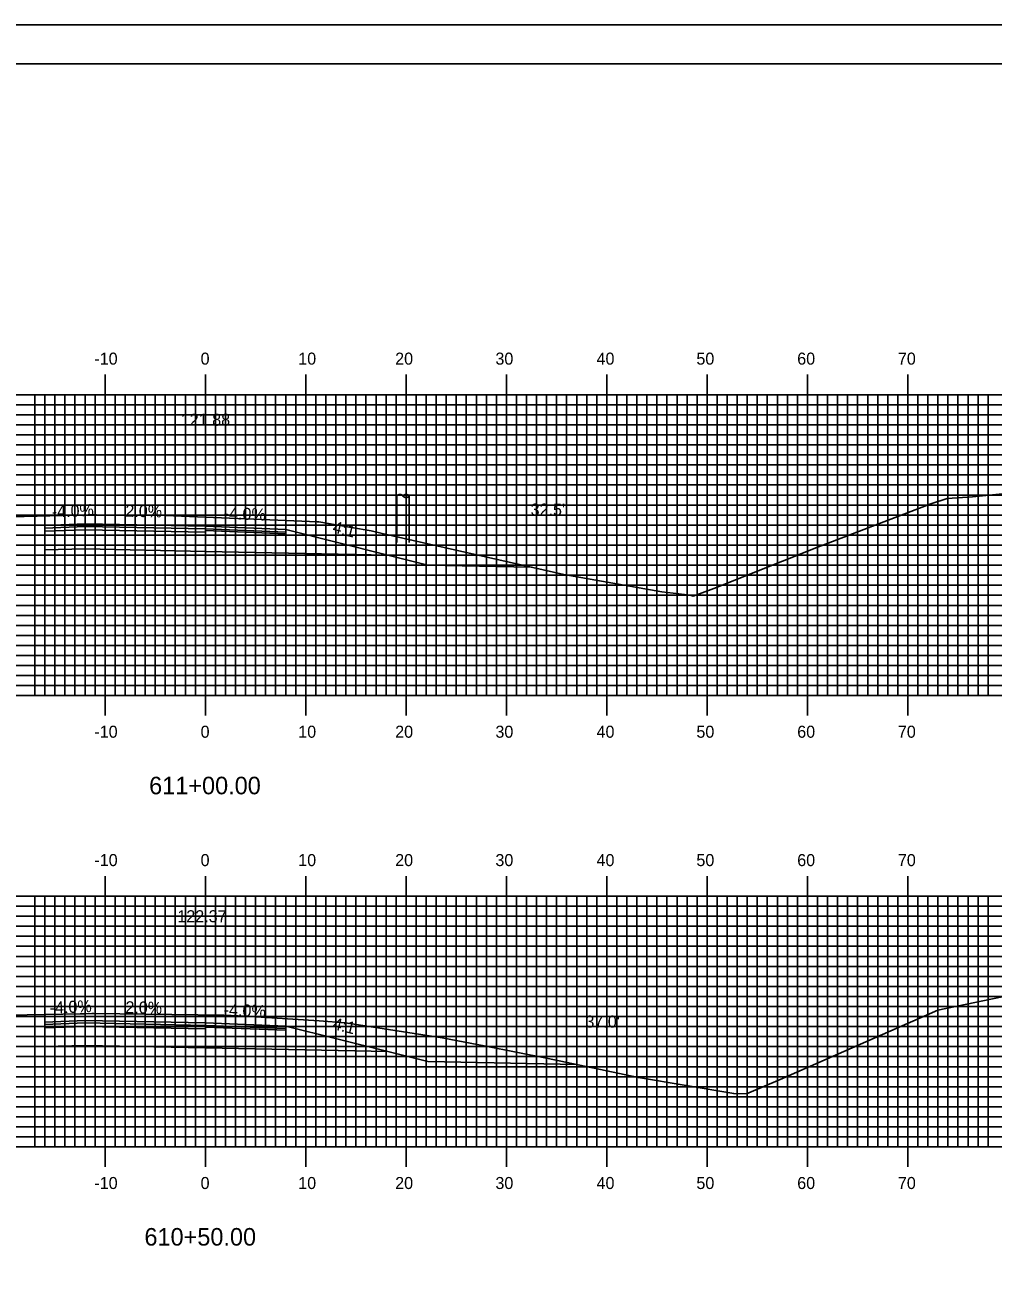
# Model space of a CAD drawing. Extents: x 843356 to 843699, y 363538 to 363758.
# Drawn here: x 843503.4 to 843599.9, y 363633.7 to 363757.6 of the extents above; entities that cross this region are included whole.
import ezdxf

# ---------------------------------------------------------------- set-up
doc = ezdxf.new("R2010")
doc.units = 0
for name, color, linetype in [('ANNOTATION', 7, 'Continuous'), ('BORDER', 7, 'Continuous'), ('D_Roadway_Centerline', 7, 'Continuous'), ('D_Roadway_Centerline_Text', 7, 'Continuous'), ('D_Roadway_Edge_Shoulder', 7, 'Continuous'), ('D_Roadway_Edge_TW', 7, 'Continuous'), ('D_Roadway_FinishedGrade', 7, 'Continuous'), ('D_Roadway_Pavement', 7, 'Continuous'), ('D_Roadway_SubGrade', 7, 'Continuous'), ('D_Text_Standard', 7, 'Continuous'), ('H_V ANNOTATION', 7, 'Continuous'), ('M_Roadway_Centerline', 7, 'Continuous'), ('MAJOR', 7, 'Continuous'), ('MINOR', 7, 'Continuous'), ('PLOT BOUNDARY', 7, 'Continuous'), ('S_Roadway_Centerline', 7, 'Continuous'), ('S_Utilities_Pole_StreetLight', 7, 'Continuous')]:
    doc.layers.add(name, color=color, linetype=linetype)

msp = doc.modelspace()

# ---------------------------------------------------------------- linework, layer by layer
at = {"layer": 'BORDER'}
msp.add_lwpolyline([(843371.82, 363543.72), (843691.82, 363543.72), (843691.82, 363753.72), (843371.82, 363753.72)], close=True, dxfattribs=at)
at = {"layer": 'D_Roadway_Centerline'}
for points in [[(843505.42, 363707.68), (843509.42, 363707.84), (843521.42, 363707.6), (843529.42, 363707.28), (843539.6, 363704.74)], [(843505.42, 363658.17), (843509.42, 363658.33), (843521.42, 363658.09), (843529.42, 363657.77), (843539.6, 363655.22)]]:
    msp.add_lwpolyline(points, dxfattribs=at)
at = {"layer": 'D_Roadway_Edge_Shoulder'}
for points in [[(843509.42, 363707.84), (843505.42, 363707.68), (843505.42, 363707.43), (843509.42, 363707.59)], [(843521.42, 363707.6), (843529.42, 363707.28), (843529.42, 363707.03), (843521.42, 363707.35)], [(843509.42, 363658.33), (843505.42, 363658.17), (843505.42, 363657.92), (843509.42, 363658.08)], [(843521.42, 363658.09), (843529.42, 363657.77), (843529.42, 363657.52), (843521.42, 363657.84)]]:
    msp.add_lwpolyline(points, close=True, dxfattribs=at)
at = {"layer": 'D_Roadway_Edge_TW'}
for points in [[(843509.42, 363707.84), (843521.42, 363707.6), (843521.42, 363707.35), (843509.42, 363707.59)], [(843509.42, 363658.33), (843521.42, 363658.09), (843521.42, 363657.84), (843509.42, 363658.08)]]:
    msp.add_lwpolyline(points, close=True, dxfattribs=at)
at = {"layer": 'D_Roadway_FinishedGrade'}
for points in [[(843539.6, 363704.74), (843543.6, 363703.74), (843553.9, 363703.53)], [(843539.6, 363655.22), (843543.6, 363654.22), (843558.44, 363653.93)]]:
    msp.add_lwpolyline(points, dxfattribs=at)
at = {"layer": 'D_Roadway_Pavement'}
for points in [[(843509.42, 363707.59), (843505.42, 363707.43), (843505.42, 363707.1), (843509.42, 363707.26)], [(843509.42, 363707.59), (843521.42, 363707.35), (843521.42, 363707.02), (843509.42, 363707.26)], [(843521.42, 363707.35), (843529.42, 363707.03), (843529.42, 363706.86), (843521.42, 363707.18)], [(843509.42, 363658.08), (843505.42, 363657.92), (843505.42, 363657.58), (843509.42, 363657.74)], [(843509.42, 363658.08), (843521.42, 363657.84), (843521.42, 363657.5), (843509.42, 363657.74)], [(843521.42, 363657.84), (843529.42, 363657.52), (843529.42, 363657.35), (843521.42, 363657.67)]]:
    msp.add_lwpolyline(points, close=True, dxfattribs=at)
for points in [[(843521.42, 363707.35), (843521.42, 363707.02)], [(843521.42, 363707.35), (843521.42, 363707.02)], [(843521.42, 363657.84), (843521.42, 363657.5)], [(843521.42, 363657.84), (843521.42, 363657.5)]]:
    msp.add_lwpolyline(points, dxfattribs=at)
at = {"layer": 'D_Roadway_SubGrade'}
for p, q in [((843505.42, 363716.36), (843505.42, 363705.26)), ((843505.42, 363666.82), (843505.42, 363655.72))]:
    msp.add_line(p, q, dxfattribs=at)
for points in [[(843509.42, 363707.26), (843505.42, 363707.1), (843505.42, 363707.43), (843505.42, 363707.68), (843505.42, 363705.26), (843509.42, 363705.34)], [(843509.42, 363707.26), (843521.42, 363707.02), (843521.42, 363705.1), (843509.42, 363705.34)], [(843521.42, 363707.02), (843521.42, 363707.35), (843529.42, 363707.03), (843529.42, 363707.28), (843539.6, 363704.74), (843521.42, 363705.1)], [(843509.42, 363657.74), (843505.42, 363657.58), (843505.42, 363657.92), (843505.42, 363658.17), (843505.42, 363655.72), (843509.42, 363655.83)], [(843509.42, 363657.74), (843521.42, 363657.5), (843521.42, 363655.59), (843509.42, 363655.83)], [(843521.42, 363657.5), (843521.42, 363657.84), (843529.42, 363657.52), (843529.42, 363657.77), (843539.6, 363655.22), (843521.42, 363655.59)]]:
    msp.add_lwpolyline(points, close=True, dxfattribs=at)
at = {"layer": 'MAJOR'}
for p, q in [((843511.42, 363722.73), (843511.42, 363720.72)), ((843521.42, 363722.73), (843521.42, 363720.72)), ((843531.42, 363722.73), (843531.42, 363720.72)), ((843541.42, 363722.73), (843541.42, 363720.72)), ((843551.42, 363722.73), (843551.42, 363720.72)), ((843561.42, 363722.73), (843561.42, 363720.72)), ((843571.42, 363722.73), (843571.42, 363720.72)), ((843581.42, 363722.73), (843581.42, 363720.72)), ((843591.42, 363722.73), (843591.42, 363720.72)), ((843381.42, 363720.72), (843661.42, 363720.72)), ((843381.42, 363720.72), (843661.42, 363720.72)), ((843511.42, 363690.72), (843511.42, 363720.72)), ((843521.42, 363690.72), (843521.42, 363720.72)), ((843531.42, 363690.72), (843531.42, 363720.72)), ((843541.42, 363690.72), (843541.42, 363720.72)), ((843551.42, 363690.72), (843551.42, 363720.72)), ((843561.42, 363690.72), (843561.42, 363720.72)), ((843571.42, 363690.72), (843571.42, 363720.72)), ((843581.42, 363690.72), (843581.42, 363720.72)), ((843591.42, 363690.72), (843591.42, 363720.72)), ((843381.42, 363715.72), (843661.42, 363715.72)), ((843381.42, 363710.72), (843661.42, 363710.72)), ((843381.42, 363705.72), (843661.42, 363705.72)), ((843381.42, 363700.72), (843661.42, 363700.72)), ((843381.42, 363695.72), (843661.42, 363695.72)), ((843381.42, 363690.72), (843661.42, 363690.72)), ((843381.42, 363690.72), (843661.42, 363690.72)), ((843511.42, 363688.72), (843511.42, 363690.72)), ((843521.42, 363688.72), (843521.42, 363690.72)), ((843531.42, 363688.72), (843531.42, 363690.72)), ((843541.42, 363688.72), (843541.42, 363690.72)), ((843551.42, 363688.72), (843551.42, 363690.72)), ((843561.42, 363688.72), (843561.42, 363690.72)), ((843571.42, 363688.72), (843571.42, 363690.72)), ((843581.42, 363688.72), (843581.42, 363690.72)), ((843591.42, 363688.72), (843591.42, 363690.72)), ((843511.42, 363672.73), (843511.42, 363670.72)), ((843521.42, 363672.73), (843521.42, 363670.72)), ((843531.42, 363672.73), (843531.42, 363670.72)), ((843541.42, 363672.73), (843541.42, 363670.72)), ((843551.42, 363672.73), (843551.42, 363670.72)), ((843561.42, 363672.73), (843561.42, 363670.72)), ((843571.42, 363672.73), (843571.42, 363670.72)), ((843581.42, 363672.73), (843581.42, 363670.72)), ((843591.42, 363672.73), (843591.42, 363670.72)), ((843381.42, 363670.72), (843661.42, 363670.72)), ((843381.42, 363670.72), (843661.42, 363670.72)), ((843511.42, 363645.72), (843511.42, 363670.72)), ((843521.42, 363645.72), (843521.42, 363670.72)), ((843531.42, 363645.72), (843531.42, 363670.72)), ((843541.42, 363645.72), (843541.42, 363670.72)), ((843551.42, 363645.72), (843551.42, 363670.72)), ((843561.42, 363645.72), (843561.42, 363670.72)), ((843571.42, 363645.72), (843571.42, 363670.72)), ((843581.42, 363645.72), (843581.42, 363670.72)), ((843591.42, 363645.72), (843591.42, 363670.72)), ((843381.42, 363665.72), (843661.42, 363665.72)), ((843381.42, 363660.72), (843661.42, 363660.72)), ((843381.42, 363655.72), (843661.42, 363655.72)), ((843381.42, 363650.72), (843661.42, 363650.72)), ((843381.42, 363645.72), (843661.42, 363645.72)), ((843381.42, 363645.72), (843661.42, 363645.72)), ((843511.42, 363643.72), (843511.42, 363645.72)), ((843521.42, 363643.72), (843521.42, 363645.72)), ((843531.42, 363643.72), (843531.42, 363645.72)), ((843541.42, 363643.72), (843541.42, 363645.72)), ((843551.42, 363643.72), (843551.42, 363645.72)), ((843561.42, 363643.72), (843561.42, 363645.72)), ((843571.42, 363643.72), (843571.42, 363645.72)), ((843581.42, 363643.72), (843581.42, 363645.72)), ((843591.42, 363643.72), (843591.42, 363645.72))]:
    msp.add_line(p, q, dxfattribs=at)
at = {"layer": 'MINOR'}
for p, q in [((843504.42, 363690.72), (843504.42, 363720.72)), ((843505.42, 363690.72), (843505.42, 363720.72)), ((843506.42, 363690.72), (843506.42, 363720.72)), ((843507.42, 363690.72), (843507.42, 363720.72)), ((843508.42, 363690.72), (843508.42, 363720.72)), ((843509.42, 363690.72), (843509.42, 363720.72)), ((843510.42, 363690.72), (843510.42, 363720.72)), ((843512.42, 363690.72), (843512.42, 363720.72)), ((843513.42, 363690.72), (843513.42, 363720.72)), ((843514.42, 363690.72), (843514.42, 363720.72)), ((843515.42, 363690.72), (843515.42, 363720.72)), ((843516.42, 363690.72), (843516.42, 363720.72)), ((843517.42, 363690.72), (843517.42, 363720.72)), ((843518.42, 363690.72), (843518.42, 363720.72)), ((843519.42, 363690.72), (843519.42, 363720.72)), ((843520.42, 363690.72), (843520.42, 363720.72)), ((843522.42, 363690.72), (843522.42, 363720.72)), ((843523.42, 363690.72), (843523.42, 363720.72)), ((843524.42, 363690.72), (843524.42, 363720.72)), ((843525.42, 363690.72), (843525.42, 363720.72)), ((843526.42, 363690.72), (843526.42, 363720.72)), ((843527.42, 363690.72), (843527.42, 363720.72)), ((843528.42, 363690.72), (843528.42, 363720.72)), ((843529.42, 363690.72), (843529.42, 363720.72)), ((843530.42, 363690.72), (843530.42, 363720.72)), ((843532.42, 363690.72), (843532.42, 363720.72)), ((843533.42, 363690.72), (843533.42, 363720.72)), ((843534.42, 363690.72), (843534.42, 363720.72)), ((843535.42, 363690.72), (843535.42, 363720.72)), ((843536.42, 363690.72), (843536.42, 363720.72)), ((843537.42, 363690.72), (843537.42, 363720.72)), ((843538.42, 363690.72), (843538.42, 363720.72)), ((843539.42, 363690.72), (843539.42, 363720.72)), ((843540.42, 363690.72), (843540.42, 363720.72)), ((843542.42, 363690.72), (843542.42, 363720.72)), ((843543.42, 363690.72), (843543.42, 363720.72)), ((843544.42, 363690.72), (843544.42, 363720.72)), ((843545.42, 363690.72), (843545.42, 363720.72)), ((843546.42, 363690.72), (843546.42, 363720.72)), ((843547.42, 363690.72), (843547.42, 363720.72)), ((843548.42, 363690.72), (843548.42, 363720.72)), ((843549.42, 363690.72), (843549.42, 363720.72)), ((843550.42, 363690.72), (843550.42, 363720.72)), ((843552.42, 363690.72), (843552.42, 363720.72)), ((843553.42, 363690.72), (843553.42, 363720.72)), ((843554.42, 363690.72), (843554.42, 363720.72)), ((843555.42, 363690.72), (843555.42, 363720.72)), ((843556.42, 363690.72), (843556.42, 363720.72)), ((843557.42, 363690.72), (843557.42, 363720.72)), ((843558.42, 363690.72), (843558.42, 363720.72)), ((843559.42, 363690.72), (843559.42, 363720.72)), ((843560.42, 363690.72), (843560.42, 363720.72)), ((843562.42, 363690.72), (843562.42, 363720.72)), ((843563.42, 363690.72), (843563.42, 363720.72)), ((843564.42, 363690.72), (843564.42, 363720.72)), ((843565.42, 363690.72), (843565.42, 363720.72)), ((843566.42, 363690.72), (843566.42, 363720.72)), ((843567.42, 363690.72), (843567.42, 363720.72)), ((843568.42, 363690.72), (843568.42, 363720.72)), ((843569.42, 363690.72), (843569.42, 363720.72)), ((843570.42, 363690.72), (843570.42, 363720.72)), ((843572.42, 363690.72), (843572.42, 363720.72)), ((843573.42, 363690.72), (843573.42, 363720.72)), ((843574.42, 363690.72), (843574.42, 363720.72)), ((843575.42, 363690.72), (843575.42, 363720.72)), ((843576.42, 363690.72), (843576.42, 363720.72)), ((843577.42, 363690.72), (843577.42, 363720.72)), ((843578.42, 363690.72), (843578.42, 363720.72)), ((843579.42, 363690.72), (843579.42, 363720.72)), ((843580.42, 363690.72), (843580.42, 363720.72)), ((843582.42, 363690.72), (843582.42, 363720.72)), ((843583.42, 363690.72), (843583.42, 363720.72)), ((843584.42, 363690.72), (843584.42, 363720.72)), ((843585.42, 363690.72), (843585.42, 363720.72)), ((843586.42, 363690.72), (843586.42, 363720.72)), ((843587.42, 363690.72), (843587.42, 363720.72)), ((843588.42, 363690.72), (843588.42, 363720.72)), ((843589.42, 363690.72), (843589.42, 363720.72)), ((843590.42, 363690.72), (843590.42, 363720.72)), ((843592.42, 363690.72), (843592.42, 363720.72)), ((843593.42, 363690.72), (843593.42, 363720.72)), ((843594.42, 363690.72), (843594.42, 363720.72)), ((843595.42, 363690.72), (843595.42, 363720.72)), ((843596.42, 363690.72), (843596.42, 363720.72)), ((843597.42, 363690.72), (843597.42, 363720.72)), ((843598.42, 363690.72), (843598.42, 363720.72)), ((843599.42, 363690.72), (843599.42, 363720.72)), ((843381.42, 363719.72), (843661.42, 363719.72)), ((843381.42, 363718.72), (843661.42, 363718.72)), ((843381.42, 363717.72), (843661.42, 363717.72)), ((843381.42, 363716.72), (843661.42, 363716.72)), ((843381.42, 363714.72), (843661.42, 363714.72)), ((843381.42, 363713.72), (843661.42, 363713.72)), ((843381.42, 363712.72), (843661.42, 363712.72)), ((843381.42, 363711.72), (843661.42, 363711.72)), ((843381.42, 363709.72), (843661.42, 363709.72)), ((843381.42, 363708.72), (843661.42, 363708.72)), ((843381.42, 363707.72), (843661.42, 363707.72)), ((843381.42, 363706.72), (843661.42, 363706.72)), ((843381.42, 363704.72), (843661.42, 363704.72)), ((843381.42, 363703.72), (843661.42, 363703.72)), ((843381.42, 363702.72), (843661.42, 363702.72)), ((843381.42, 363701.72), (843661.42, 363701.72)), ((843381.42, 363699.72), (843661.42, 363699.72)), ((843381.42, 363698.72), (843661.42, 363698.72)), ((843381.42, 363697.72), (843661.42, 363697.72)), ((843381.42, 363696.72), (843661.42, 363696.72)), ((843381.42, 363694.72), (843661.42, 363694.72)), ((843381.42, 363693.72), (843661.42, 363693.72)), ((843381.42, 363692.72), (843661.42, 363692.72)), ((843381.42, 363691.72), (843661.42, 363691.72)), ((843381.42, 363669.72), (843661.42, 363669.72)), ((843504.42, 363645.72), (843504.42, 363670.72)), ((843505.42, 363645.72), (843505.42, 363670.72)), ((843506.42, 363645.72), (843506.42, 363670.72)), ((843507.42, 363645.72), (843507.42, 363670.72)), ((843508.42, 363645.72), (843508.42, 363670.72)), ((843509.42, 363645.72), (843509.42, 363670.72)), ((843510.42, 363645.72), (843510.42, 363670.72)), ((843512.42, 363645.72), (843512.42, 363670.72)), ((843513.42, 363645.72), (843513.42, 363670.72)), ((843514.42, 363645.72), (843514.42, 363670.72)), ((843515.42, 363645.72), (843515.42, 363670.72)), ((843516.42, 363645.72), (843516.42, 363670.72)), ((843517.42, 363645.72), (843517.42, 363670.72)), ((843518.42, 363645.72), (843518.42, 363670.72)), ((843519.42, 363645.72), (843519.42, 363670.72)), ((843520.42, 363645.72), (843520.42, 363670.72)), ((843522.42, 363645.72), (843522.42, 363670.72)), ((843523.42, 363645.72), (843523.42, 363670.72)), ((843524.42, 363645.72), (843524.42, 363670.72)), ((843525.42, 363645.72), (843525.42, 363670.72)), ((843526.42, 363645.72), (843526.42, 363670.72)), ((843527.42, 363645.72), (843527.42, 363670.72)), ((843528.42, 363645.72), (843528.42, 363670.72)), ((843529.42, 363645.72), (843529.42, 363670.72)), ((843530.42, 363645.72), (843530.42, 363670.72)), ((843532.42, 363645.72), (843532.42, 363670.72)), ((843533.42, 363645.72), (843533.42, 363670.72)), ((843534.42, 363645.72), (843534.42, 363670.72)), ((843535.42, 363645.72), (843535.42, 363670.72)), ((843536.42, 363645.72), (843536.42, 363670.72)), ((843537.42, 363645.72), (843537.42, 363670.72)), ((843538.42, 363645.72), (843538.42, 363670.72)), ((843539.42, 363645.72), (843539.42, 363670.72)), ((843540.42, 363645.72), (843540.42, 363670.72)), ((843542.42, 363645.72), (843542.42, 363670.72)), ((843543.42, 363645.72), (843543.42, 363670.72)), ((843544.42, 363645.72), (843544.42, 363670.72)), ((843545.42, 363645.72), (843545.42, 363670.72)), ((843546.42, 363645.72), (843546.42, 363670.72)), ((843547.42, 363645.72), (843547.42, 363670.72)), ((843548.42, 363645.72), (843548.42, 363670.72)), ((843549.42, 363645.72), (843549.42, 363670.72)), ((843550.42, 363645.72), (843550.42, 363670.72)), ((843552.42, 363645.72), (843552.42, 363670.72)), ((843553.42, 363645.72), (843553.42, 363670.72)), ((843554.42, 363645.72), (843554.42, 363670.72)), ((843555.42, 363645.72), (843555.42, 363670.72)), ((843556.42, 363645.72), (843556.42, 363670.72)), ((843557.42, 363645.72), (843557.42, 363670.72)), ((843558.42, 363645.72), (843558.42, 363670.72)), ((843559.42, 363645.72), (843559.42, 363670.72)), ((843560.42, 363645.72), (843560.42, 363670.72)), ((843562.42, 363645.72), (843562.42, 363670.72)), ((843563.42, 363645.72), (843563.42, 363670.72)), ((843564.42, 363645.72), (843564.42, 363670.72)), ((843565.42, 363645.72), (843565.42, 363670.72)), ((843566.42, 363645.72), (843566.42, 363670.72)), ((843567.42, 363645.72), (843567.42, 363670.72)), ((843568.42, 363645.72), (843568.42, 363670.72)), ((843569.42, 363645.72), (843569.42, 363670.72)), ((843570.42, 363645.72), (843570.42, 363670.72)), ((843572.42, 363645.72), (843572.42, 363670.72)), ((843573.42, 363645.72), (843573.42, 363670.72)), ((843574.42, 363645.72), (843574.42, 363670.72)), ((843575.42, 363645.72), (843575.42, 363670.72)), ((843576.42, 363645.72), (843576.42, 363670.72)), ((843577.42, 363645.72), (843577.42, 363670.72)), ((843578.42, 363645.72), (843578.42, 363670.72)), ((843579.42, 363645.72), (843579.42, 363670.72)), ((843580.42, 363645.72), (843580.42, 363670.72)), ((843582.42, 363645.72), (843582.42, 363670.72)), ((843583.42, 363645.72), (843583.42, 363670.72)), ((843584.42, 363645.72), (843584.42, 363670.72)), ((843585.42, 363645.72), (843585.42, 363670.72)), ((843586.42, 363645.72), (843586.42, 363670.72)), ((843587.42, 363645.72), (843587.42, 363670.72)), ((843588.42, 363645.72), (843588.42, 363670.72)), ((843589.42, 363645.72), (843589.42, 363670.72)), ((843590.42, 363645.72), (843590.42, 363670.72)), ((843592.42, 363645.72), (843592.42, 363670.72)), ((843593.42, 363645.72), (843593.42, 363670.72)), ((843594.42, 363645.72), (843594.42, 363670.72)), ((843595.42, 363645.72), (843595.42, 363670.72)), ((843596.42, 363645.72), (843596.42, 363670.72)), ((843597.42, 363645.72), (843597.42, 363670.72)), ((843598.42, 363645.72), (843598.42, 363670.72)), ((843599.42, 363645.72), (843599.42, 363670.72)), ((843381.42, 363668.72), (843661.42, 363668.72)), ((843381.42, 363667.72), (843661.42, 363667.72)), ((843381.42, 363666.72), (843661.42, 363666.72)), ((843381.42, 363664.72), (843661.42, 363664.72)), ((843381.42, 363663.72), (843661.42, 363663.72)), ((843381.42, 363662.72), (843661.42, 363662.72)), ((843381.42, 363661.72), (843661.42, 363661.72)), ((843381.42, 363659.72), (843661.42, 363659.72)), ((843381.42, 363658.72), (843661.42, 363658.72)), ((843381.42, 363657.72), (843661.42, 363657.72)), ((843381.42, 363656.72), (843661.42, 363656.72)), ((843381.42, 363654.72), (843661.42, 363654.72)), ((843381.42, 363653.72), (843661.42, 363653.72)), ((843381.42, 363652.72), (843661.42, 363652.72)), ((843381.42, 363651.72), (843661.42, 363651.72)), ((843381.42, 363649.72), (843661.42, 363649.72)), ((843381.42, 363648.72), (843661.42, 363648.72)), ((843381.42, 363647.72), (843661.42, 363647.72)), ((843381.42, 363646.72), (843661.42, 363646.72))]:
    msp.add_line(p, q, dxfattribs=at)
at = {"layer": 'PLOT BOUNDARY'}
msp.add_lwpolyline([(843355.64, 363537.6), (843695.64, 363537.6), (843695.64, 363757.6), (843355.64, 363757.6)], close=True, dxfattribs=at)
at = {"layer": 'S_Roadway_Centerline'}
for points in [[(843502.08, 363708.53), (843509.73, 363708.75), (843510.55, 363708.76), (843513.54, 363708.71), (843514.45, 363708.71), (843517.43, 363708.67), (843531.03, 363708.1), (843532.54, 363708.04), (843532.72, 363708.04), (843535.99, 363707.48), (843537.93, 363707.14), (843539.05, 363706.88), (843557.14, 363702.8), (843566.91, 363701.07), (843569.73, 363700.74), (843570.02, 363700.62), (843572.1, 363701.41), (843582.35, 363705.5), (843593.71, 363709.85), (843595.33, 363710.36), (843597.86, 363710.54), (843607.79, 363711.53)], [(843496.11, 363658.76), (843505.52, 363658.93), (843508.93, 363659), (843509.41, 363659), (843510.11, 363659.02), (843510.3, 363659.03), (843510.31, 363659.03), (843523.24, 363658.84), (843525.4, 363658.77), (843532.76, 363658.3), (843535.38, 363658.09), (843545.02, 363656.6), (843549.36, 363655.78), (843555.42, 363654.56), (843564.58, 363652.63), (843574.07, 363651.04), (843575.33, 363651), (843578.7, 363652.43), (843594.41, 363659.36), (843601.78, 363660.88)]]:
    msp.add_lwpolyline(points, dxfattribs=at)
at = {"layer": 'S_Utilities_Pole_StreetLight'}
for p, q in [((843540.48, 363710.62), (843540.64, 363710.73)), ((843540.48, 363706), (843540.48, 363710.62)), ((843540.95, 363710.73), (843541.11, 363710.62)), ((843541.27, 363710.73), (843541.11, 363710.62)), ((843541.11, 363710.62), (843541.27, 363710.51)), ((843541.73, 363710.62), (843541.58, 363710.73)), ((843541.58, 363710.51), (843541.73, 363710.62)), ((843541.73, 363706), (843541.73, 363710.62))]:
    msp.add_line(p, q, dxfattribs=at)
for centre, start, end in [((843540.8, 363710.51), 90, 125.2644), ((843540.8, 363710.51), 54.7356, 90), ((843541.42, 363710.51), 90, 125.2644), ((843541.42, 363710.73), 234.7356, 270), ((843541.42, 363710.51), 54.7356, 90), ((843541.42, 363710.73), 270, 305.2644)]:
    msp.add_arc(centre, 0.271, start, end, dxfattribs=at)

# ---------------------------------------------------------------- texts
at = {"layer": 'ANNOTATION'}
for s, rotation, p in [('-4.0%', 2.2906, (843506.13, 363708.47)), ('2.0%', 358.8542, (843513.43, 363708.56)), ('-4.0%', 357.7094, (843523.22, 363708.33)), ('4:1', 345.9638, (843534.02, 363707)), ('-4.0%', 2.2906, (843505.92, 363659)), ('2.0%', 358.8542, (843513.43, 363659.05)), ('-4.0%', 357.7094, (843523.22, 363658.82)), ('4:1', 345.9638, (843534.02, 363657.48))]:
    msp.add_text(s, height=1.2, rotation=rotation, dxfattribs=at).set_placement(p)
at = {"layer": 'D_Roadway_Centerline_Text'}
for s, p in [('121.88', (843518.97, 363717.63)), ('122.37', (843518.62, 363668.12))]:
    msp.add_text(s, height=1.2, dxfattribs=at).set_placement(p)
at = {"layer": 'D_Text_Standard'}
for s, p in [("32.5'", (843553.83, 363708.67)), ("37.0'", (843559.29, 363657.62))]:
    msp.add_text(s, height=1.2, dxfattribs=at).set_placement(p)
at = {"layer": 'H_V ANNOTATION'}
for s, height, p in [('-10', 1.2, (843510.35, 363723.72)), ('0', 1.2, (843520.94, 363723.72)), ('10', 1.2, (843530.67, 363723.72)), ('20', 1.2, (843540.33, 363723.72)), ('30', 1.2, (843550.32, 363723.72)), ('40', 1.2, (843560.4, 363723.72)), ('50', 1.2, (843570.35, 363723.72)), ('60', 1.2, (843580.4, 363723.72)), ('70', 1.2, (843590.43, 363723.72)), ('-10', 1.2, (843510.35, 363686.52)), ('0', 1.2, (843520.94, 363686.52)), ('10', 1.2, (843530.67, 363686.52)), ('20', 1.2, (843540.33, 363686.52)), ('30', 1.2, (843550.32, 363686.52)), ('40', 1.2, (843560.4, 363686.52)), ('50', 1.2, (843570.35, 363686.52)), ('60', 1.2, (843580.4, 363686.52)), ('70', 1.2, (843590.43, 363686.52)), ('611+00.00', 1.75, (843515.81, 363680.88)), ('-10', 1.2, (843510.35, 363673.72)), ('0', 1.2, (843520.94, 363673.72)), ('10', 1.2, (843530.67, 363673.72)), ('20', 1.2, (843540.33, 363673.72)), ('30', 1.2, (843550.32, 363673.72)), ('40', 1.2, (843560.4, 363673.72)), ('50', 1.2, (843570.35, 363673.72)), ('60', 1.2, (843580.4, 363673.72)), ('70', 1.2, (843590.43, 363673.72)), ('-10', 1.2, (843510.35, 363641.52)), ('0', 1.2, (843520.94, 363641.52)), ('10', 1.2, (843530.67, 363641.52)), ('20', 1.2, (843540.33, 363641.52)), ('30', 1.2, (843550.32, 363641.52)), ('40', 1.2, (843560.4, 363641.52)), ('50', 1.2, (843570.35, 363641.52)), ('60', 1.2, (843580.4, 363641.52)), ('70', 1.2, (843590.43, 363641.52)), ('610+50.00', 1.75, (843515.34, 363635.88))]:
    msp.add_text(s, height=height, dxfattribs=at).set_placement(p)
at = {"layer": 'M_Roadway_Centerline'}
for s, p in [('C', (843510.55, 363708.76)), ('L', (843510.55, 363708.75)), ('C', (843510.29, 363659.03)), ('L', (843510.3, 363659.02))]:
    msp.add_text(s, height=0.0146, dxfattribs=at).set_placement(p)

doc.saveas('drawing.dxf')
